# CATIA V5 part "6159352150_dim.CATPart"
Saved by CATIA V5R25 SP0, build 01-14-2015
Part number: 6159352150_dim
Source: made
Property "PROI_CREATED_ON": "12/17/2008 9:21:37 AM"
Property "BLANK_DRAWING": "--"
Property "DRAWN_BY": "FPA"
Property "FINISH": "--"
Property "HEAT_TREATMENT": "ASSIGN"
Property "MATERIAL": "ASSIGN"
Property "PROJECT": "--"
Property "PROTOTYPE_NO": "--"
Property "RELATED_DRAWING": "--"
Property "COMPLETE_MATERIAL": "ASSIGN-ASSIGN"
Property "DESCRIPTION": "Q-SHIELD 800-S"
Property "DRAWING_EXIST": "--"
Property "MANUFACTURER": "--"
Property "MANUFACTURER_2": "--"
Property "MANUFACTURER_REF": "--"
Property "TYPE_PART": "--"
Property "TODAY_DATE": "2021/06/10"
Property "PDMREV": "01.0"
Property "PDMRL": "Production"
Property "PROI_REVISION": "01"
Property "PROI_VERSION": "0"
Property "PROI_RELEASE": "Production"
Property "PTC_MODIFIED": false
Property "MFG_WP_MATERIAL": "ASSIGN"
Property "COMPANY_CODE": "---"
Property "DESCRIPTION_JP": "--"
Property "PQP_DOCUMENT": "--"
Property "GHOST": false
Property "NO_PART": false
Property "PTC_WM_ITERATION": "0"
Property "PTC_WM_VERSION": "01.0"
Property "PTC_WM_CREATED_ON": "10-Jun-21 02:52:31 PM"
Property "PTC_WM_MODIFIED_ON": "10-Jun-21 03:21:17 PM"
Property "PTC_WM_NAME": "6159352150_dim.prt"
Property "PTC_WM_NUMBER": "6159352150_DIM.PRT"
Property "PTC_WM_LIFECYCLE_STATE": "Production"
Property "PTC_WM_LIFECYCLE": "Design_Process"
Property "PTC_WM_REVISION": "01"
Property "PTC_WM_CREATED_BY": "Florian Pavageau (Grefpav) (Grefpav: CPD)"
Property "PTC_WM_MODIFIED_BY": "Florian Pavageau (Grefpav) (Grefpav: CPD)"
Property "PTC_ORGANIZATION_ID": "CPD"
Property "PTC_WM_LOCATION": "/Products/TORQUE MEASUREMENT SYSTEMS/A2010 - DELTAWRENCH GEN2/9-01-Dimensional D"
Property "PTC_WM_PART_NAME": "6159352150_dim.prt"
Property "PTC_WM_PART_NUMBER": "6159352150_DIM"
Property "PTC_WM_TEAM": "Default"
Property "EXPORT_CONTROL": "NULL"
Property "PTC_COMMON_NAME": "6159352150_dim.prt"
Property "PTC_MASTER_MATERIAL": "ASSIGN"
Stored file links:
  d:\ptc\Echange\temp\6159352150_dim.CATPart

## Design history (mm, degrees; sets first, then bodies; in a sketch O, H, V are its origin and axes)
AxisSystem1 "CS0": origin (0, 0, 0), X (1, 0, 0), Y (0, 1, 0), Z (0, 0, 1)
Set1
  DatumSurface1 "Sheet.1"
  DatumSurface2 "Sheet.2"
  DatumSurface3 "Sheet.3"
  DatumSurface4 "Sheet.4"
  DatumSurface5 "Sheet.5"
  DatumSurface6 "Sheet.6"
  DatumSurface7 "Sheet.7"
  DatumSurface8 "Sheet.8"
  DatumSurface9 "Sheet.9"
  Plane1 "RIGHT": stored without definition
  Plane2 "TOP": stored without definition
  Plane3 "FRONT": stored without definition
Body1 "PartBody" (main body)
